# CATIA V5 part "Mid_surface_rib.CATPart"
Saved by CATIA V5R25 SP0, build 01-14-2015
Part number: Part1
Bounding box of the stored display mesh (mm): x -50 to 50, y -7.836 to 79.398, z 0 to 79.208
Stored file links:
  E:\cadcim\GSD_cat_v5-6r2014\Part_files\Mid_surface_rib.CATPart
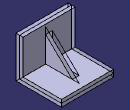
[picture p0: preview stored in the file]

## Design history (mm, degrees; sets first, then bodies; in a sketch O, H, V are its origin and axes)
Body1 (main body)
  Sketch1 on yz-plane, origin (0, 0, 0), H (0, 1, 0), V (0, 0, 1)
    line L1 (5.5044, 79.2082) -> (-7.8364, 79.2082)
    line L2 (-7.8364, 79.2082) -> (-7.8364, 0)
    point P3 (-7.8364, 0)
    line L3 (-7.8364, 0) -> (79.3978, 0)
    line L4 (79.3978, 0) -> (79.3978, 12.9983)
    line L5 (79.3978, 12.9983) -> (5.5044, 12.9983)
    line L6 (5.5044, 12.9983) -> (5.5044, 79.2082)
    horizontal: L1 H, L5 H, L3 H
    coincidence: P3 H
    vertical: L4 V, L6 V, L2 V
    parallelism: L5 L3
  Pad1: profile Sketch1, direction (-1, 0, 0), length 50, mirrored extent
  Sketch2 on yz-plane, origin (0, 0, 0), H (0, 1, 0), V (0, 0, 1)
    line L1 (56.7612, 12.9983) -> (5.5044, 61.9732)
    point P1 (56.7612, 12.9983)
    point P2 (5.5044, 61.9732)
    reference projected line E1 (5.5044, 18.7088) -> (5.5044, 69.2026) from edge [face of Pad1 from Sketch1.L6 | start face of Pad1]
    reference projected line E2 (79.0467, 12.9983) -> (8.5173, 12.9983) from edge [face of Pad1 from Sketch1.L5 | start face of Pad1]
    coincidence: P2 E1, P1 E2
  Stiffener1: ExtendedProfile Sketch2, ThicknessTop 0, ThicknessValue 13
  MidSurface1: InputSolid Stiffener1, FacePairs ({midsurfacefacepair Face1 face of Pad1 from Sketch1.L6, Face2 face of Pad1 from Sketch1.L2}; {midsurfacefacepair Face1 face of Pad1 from Sketch1.L5, Face2 face of Pad1 from Sketch1.L3}), OffsetRatio 0.5
  MidSurface2: InputSolid Stiffener1, FacePairs {midsurfacefacepair Face1 face of Stiffener1, Face2 face of Stiffener1}, OffsetRatio 0.5, LimitingMidSurface MidSurface1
